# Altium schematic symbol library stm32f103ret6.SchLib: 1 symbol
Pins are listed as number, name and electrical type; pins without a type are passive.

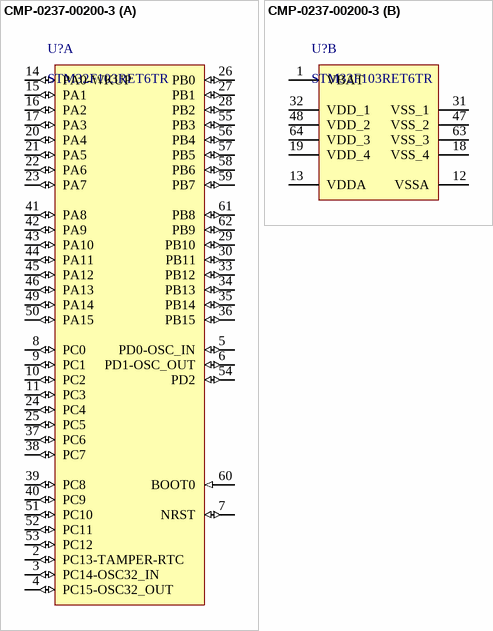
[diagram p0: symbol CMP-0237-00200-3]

## CMP-0237-00200-3
designator U?, comment STM32F103RET6TR
ARM Cortex-M3 32-bit MCU, 512 KB Flash, 64 KB Internal RAM, 51 I/Os, 64-pin LQFP, -40 to 85 degC, Tape and Reel; A/D Converter: 3x12-bit (16 Channel); I/Os (High Current): 51; Internal RAM Size (kB): 64; Operating Frequency(F) (Processor speed) (MHz): 72; D/A Converter: 2x12-bit (2 Channel); FLASH Size (Prog) (kB): 512; Supply Voltage(Vcc) min (V): 2
footprint STM-LQFP64_L (Thin QFP, 64-Leads, Body 10x10mm, Pitch 0.5mm, IPC High Density)
footprint STM-LQFP64_N (Thin QFP, 64-Leads, Body 10x10mm, Pitch 0.5mm, IPC Medium Density)
footprint STM-LQFP64_V (Thin QFP, 64-Leads, Body 10x10mm, Pitch 0.5mm, ST Recommended)
footprint STM-LQFP64_M (Thin QFP, 64-Leads, Body 10x10mm, Pitch 0.5mm, IPC Low Density)
part A pins: 2 PC13-TAMPER-RTC (io) "PC13-TAMPER-RTC/PC13/TAMPER-RTC", 3 PC14-OSC32_IN (io) "PC14-OSC32_IN/PC14/OSC32_IN", 4 PC15-OSC32_OUT (io) "PC15-OSC32_OUT/PC15/OSC32_OUT", 5 PD0-OSC_IN (io) "PD0/OSC_IN/CAN_RX", 6 PD1-OSC_OUT (io) "PD1/OSC_OUT/CAN_TX", 7 NRST (io), 8 PC0 (io) "PC0/ADC123_IN10", 9 PC1 (io) "PC1/ADC123_IN11", 10 PC2 (io) "PC2/ADC123_IN12", 11 PC3 (io) "PC3/ADC123_IN13", 14 PA0-WKUP (io) "PA0-WKUP/PA0/WKUP/USART2_CTS/ADC123_IN0/TIM2_CH1_ETR/TIM5_CH1/TIM8_ETR", 15 PA1 (io) "PA1/USART2_RTS/ADC123_IN1/TIM5_CH2/TIM2_CH2", 16 PA2 (io) "PA2/USART2_TX/TIM5_CH3/ADC123_IN2/TIM2_CH3", 17 PA3 (io) "PA3/USART2_RX/TIM5_CH4/ADC123_IN3/TIM2_CH4", 20 PA4 (io) "PA4/SPI1_NSS/USART2_CK/DAC_OUT1/ADC12_IN4", 21 PA5 (io) "PA5/SPI1_SCK/DAC_OUT2/ADC12_IN5", 22 PA6 (io) "PA6/SPI1_MISO/TIM8_BKIN/ADC12_IN6/TIM3_CH1/TIM1_BKIN", 23 PA7 (io) "PA7/SPI1_MOSI/TIM8_CH1N/ADC12_IN7/TIM3_CH2/TIM1_CH1N", 24 PC4 (io) "PC4/ADC12_IN14", 25 PC5 (io) "PC5/ADC12_IN15", 26 PB0 (io) "PB0/ADC12_IN8/TIM3_CH3/TIM8_CH2N/TIM1_CH2N", 27 PB1 (io) "PB1/ADC12_IN9/TIM3_CH4/TIM8_CH3N/TIM1_CH3N", 28 PB2 (io) "PB2/BOOT1", 29 PB10 (io) "PB10/I2C2_SCL/USART3_TX/TIM2_CH3", 30 PB11 (io) "PB11/I2C2_SDA/USART3_RX/TIM2_CH4", 33 PB12 (io) "PB12/SPI2_NSS/I2S2_WS/I2C2_SMBA/USART3_CK/TIM1_BKIN", 34 PB13 (io) "PB13/SPI2_SCK/I2S2_CK/USART3_CTS/TIM1_CH1N", 35 PB14 (io) "PB14/SPI2_MISO/TIM1_CH2N/USART3_RTS", 36 PB15 (io) "PB15/SPI2_MOSI/I2S2_SD/TIM1_CH3N", 37 PC6 (io) "PC6/I2S2_MCK/TIM8_CH1/SDIO_D6/TIM3_CH1", 38 PC7 (io) "PC7/I2S3_MCK/TIM8_CH2/SDIO_D7/TIM3_CH2", 39 PC8 (io) "PC8/TIM8_CH3/SDIO_D0/TIM3_CH3", 40 PC9 (io) "PC9/TIM8_CH4/SDIO_D1/TIM3_CH4", 41 PA8 (io) "PA8/USART1_CK/TIM1_CH1/MCO", 42 PA9 (io) "PA9/USART1_TX/TIM1_CH2", 43 PA10 (io) "PA10/USART1_RX/TIM1_CH3", 44 PA11 (io) "PA11/USART1_CTS/USBDM/CAN_RX/TIM1_CH4", 45 PA12 (io) "PA12/USART1_RTS/USBDP/CAN_TX/TIM1_ETR", 46 PA13 (io) "PA13/JTMS-SWDIO", 49 PA14 (io) "PA14/JTCK-SWCLK", 50 PA15 (io) "PA15/JTDI/SPI3_NSS/I2S3_WS/TIM2_CH1_ETR/SPI1_NSS", 51 PC10 (io) "PC10/UART4_TX/SDIO_D2/USART3_TX", 52 PC11 (io) "PC11/UART4_RX/SDIO_D3/USART3_RX", 53 PC12 (io) "PC12/UART5_TX/SDIO_CK/USART3_CK", 54 PD2 (io) "PD2/TIM3_ETR/UART5_RX/SDIO_CMD", 55 PB3 (io) "PB3/JTDO/SPI3_SCK/I2S3_CK/TRACESWO/TIM2_CH2/SPI1_SCK", 56 PB4 (io) "PB4/NJTRST/SPI3_MISO/TIM3_CH1/SPI1_MISO", 57 PB5 (io) "PB5/I2C1_SMBA/SPI3_MOSI/I2S3_SD/TIM3_CH2/SPI1_MOSI", 58 PB6 (io) "PB6/I2C1_SCL/TIM4_CH1/USART1_TX", 59 PB7 (io) "PB7/I2C1_SDA/TIM4_CH2/USART1_RX", 60 BOOT0 (in), 61 PB8 (io) "PB8/TIM4_CH3/SDIO_D4/I2C1_SCL/CAN_RX", 62 PB9 (io) "PB9/TIM4_CH4/SDIO_D5/I2C1_SDA/CAN_TX"
part B pins: 1 VBAT (power), 12 VSSA (power), 13 VDDA (power), 18 VSS_4 (power), 19 VDD_4 (power), 31 VSS_1 (power), 32 VDD_1 (power), 47 VSS_2 (power), 48 VDD_2 (power), 63 VSS_3 (power), 64 VDD_3 (power)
